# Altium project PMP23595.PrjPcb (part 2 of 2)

## Sheet DynamicLoad.SchDoc
size 431 x 279 mm; Date: Not shown in title block; ApprovedBy: Not shown in title block; CheckedBy: Not shown in title block; Author: Not shown in title block; CompanyName: Not shown in title block; Engineer: Not shown in title block; Organization: Not shown in title block; Address1: Not shown in title block; Address2: Not shown in title block; Address3: Not shown in title block; Address4: Not shown in title block; DocumentNumber: 2; Revision: Use project parameter SCH_Rev; SheetNumber: 2; SheetTotal: 3; PageSetup: Record=PageOptions¦CenterHorizontal=True¦CenterVertical=True¦PrintScale=1.00¦XCorrection=1.00¦YCorrection=1.00¦PrintKind=0¦BorderSize=5000000¦LeftOffset=0¦BottomOffset=0¦Orientation=2¦PaperLength=1000¦PaperWidth=1000¦Scale=100¦PaperSource=15¦PrintQuality=600¦MediaType=1¦DitherType=10¦PaperKind=Letter¦PrintScaleMode=1
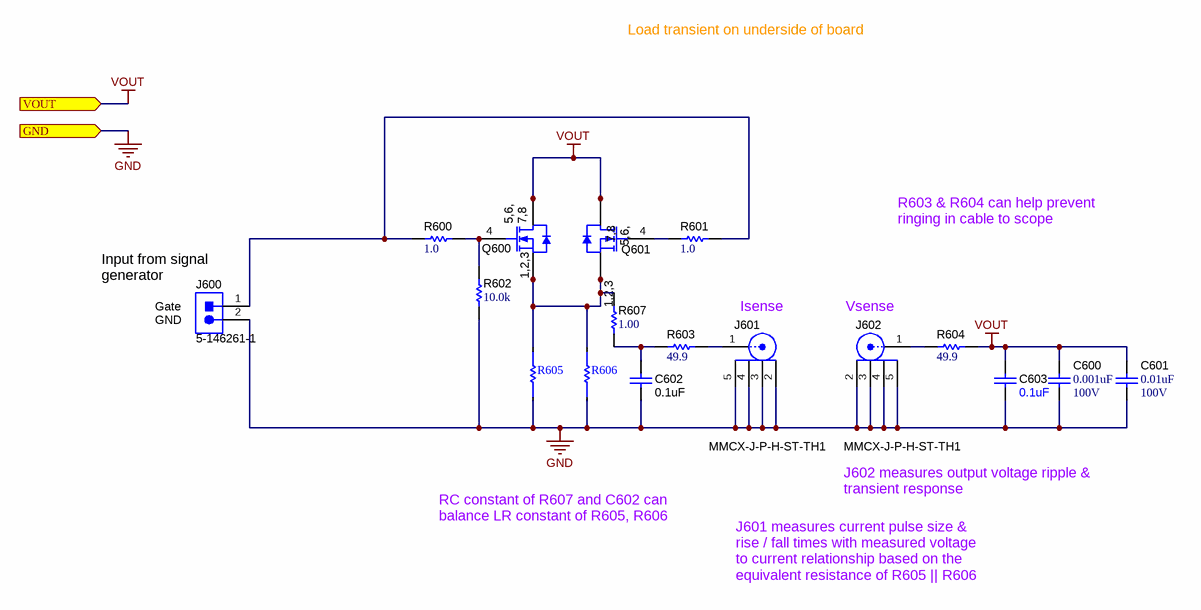
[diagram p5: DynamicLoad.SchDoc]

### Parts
C600  Cap_F: 0.001uF  VDC_V: 100V  [0603L]  (hidden comment: CGA3E2X7R2A102K080AA)
C601  Value2: 100V  ValueDisplayed: 0.01uF  [0603L]  (hidden comment: GRM188R72A103KA01D)
C602  ValueDisplayed: 0.1uF  [0603L]  (hidden comment: CGA3E2X7R1E104K080AA)
C603  ValueDisplayed: 0.1uF  [0603L]  (hidden comment: CGA3E2X7R1E104K080AA)
J600  5-146261-1  [CONN_5-146261-1]
J601  MMCX-J-P-H-ST-TH1  [Samtec_MMCX-J-P-H-ST-TH1]
J602  MMCX-J-P-H-ST-TH1  [Samtec_MMCX-J-P-H-ST-TH1]
Q600  CSD17570Q5B  [DNK0008A]  (value not drawn)
Q601  CSD17570Q5B  [DNK0008A]  (value not drawn)
R600  ValueDisplayed: 1.0  [0603L]  (hidden comment: CRCW06031R00JNEA)
R601  ValueDisplayed: 1.0  [0603L]  (hidden comment: CRCW06031R00JNEA)
R602  ValueDisplayed: 10.0k  [0603L]  (hidden comment: CRCW060310K0FKEA)
R603  ValueDisplayed: 49.9  [0603L]  (hidden comment: CRCW060349R9FKEA)
R604  ValueDisplayed: 49.9  [0603L]  (hidden comment: CRCW060349R9FKEA)
R605  WK73S3ATTER200F  [FP-WK73S3ATTER200F_1225-MFG]  (value not drawn)
R606  WK73S3ATTER200F  [FP-WK73S3ATTER200F_1225-MFG]  (value not drawn)
R607  ValueDisplayed: 1.00  [0603L]  (hidden comment: CRCW06031R00FKEA)

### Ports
GND (in), VOUT (in)

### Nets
GND: C600.2 C601.1 C602.1 C603.1 J600.2 J601.2 J601.3 J601.4 J601.5 J602.2 J602.3 J602.4 J602.5 R602.1 R605.1 R606.1 ; port GND
VOUT: C600.1 C601.2 C603.2 Q600.5(D) Q600.6(D) Q600.7(D) Q600.8(D) Q600.9(D) Q601.5(D) Q601.6(D) Q601.7(D) Q601.8(D) Q601.9(D) R604.2 ; port VOUT
NetC602_2: C602.2 R603.1 R607.1
NetJ600_1: J600.1 R600.2 R601.1
NetJ601_1: J601.1 R603.2
NetJ602_1: J602.1 R604.1
NetQ600_1: Q600.1(S) Q600.2(S) Q600.3(S) Q601.1(S) Q601.2(S) Q601.3(S) R605.2 R606.2 R607.2
NetQ600_4: Q600.4(G) R600.1 R602.2
NetQ601_4: Q601.4(G) R601.2

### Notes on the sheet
- Load transient on underside of board
- R603 & R604 can help prevent ringing in cable to scope
- (near J600) Input from signal generator
- (near J600) Gate
- (near J600) GND
- (near J601) Isense
- (near J602) Vsense
- J602 measures output voltage ripple & transient response
- RC constant of R607 and C602 can balance LR constant of R605, R606
- J601 measures current pulse size & rise / fall times with measured voltage to current relationship based on the equivalent resistance of R605 || R606

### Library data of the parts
C600 = CMP-0007081-4: CAP, CERM, 1000 pF, 100 V, +/- 10%, X7R, AEC-Q200 Grade 1, 0603; Manufacturer: TDK; TaMin_C: -55°C; ESR_ohm: 1.9714; Polarized: N; SizeAreaWB_mm2: 4.68; Value1: 1.97137 ohm; U/M: EA; Value: 1000pF; TaMax_C: 125°C; SizeZ_mm: 1; SizeX_mm: 1.6; SizeY_mm: 0.8; Cap_Case: 0603; SizeArea_mm2: 1.28; AEC Qualified: Y; IRMS_A: 305.705mA; AEC Category: Q200
C601 = CMP-0007468-5: CAP, CERM, 0.01 uF, 100 V, +/- 10%, X7R, 0603; Manufacturer: MuRata; TaMin_C: -55°C; Polarized: N; SizeAreaWB_mm2: 4.68; Value1: Unknown; U/M: EA; Value: 0.01uF; TaMax_C: 125°C; SizeZ_mm: 1; SizeX_mm: 1.6; SizeY_mm: 0.8; Cap_Case: 0603; SizeArea_mm2: 1.28; Cap_F: 10nF; AEC Category: Q200
C602 C603 = CMP-0007077-5: CAP, CERM, 0.1 uF, 25 V, +/- 10%, X7R, AEC-Q200 Grade 1, 0603; Manufacturer: TDK; TaMin_C: -55°C; Polarized: N; SizeAreaWB_mm2: 4.68; Value1: Unknown; U/M: EA; Value: 0.1uF; TaMax_C: 125°C; SizeZ_mm: 1; SizeX_mm: 1.6; SizeY_mm: 0.8; Cap_Case: 0603; Value2: 25V; SizeArea_mm2: 1.28; AEC Qualified: Y; Cap_F: 100nF; AEC Category: Q200
J600 = CMP-0054947-1: Header, 100mil, 2x1, Gold, TH; Manufacturer: TE Connectivity; Green_Lifecycle: Active; Green_REACh: Passed; CNHeader: TRUE; CT: FALSE
J601 J602 = CMP-0075554-1: Connector, MMCX 50 ohm, TH; Manufacturer: Samtec; CT: False; Gender: Female
Q600 Q601 = CMP-0000584-2: MOSFET, N-CH, 30 V, 51 A, DNK0008A (VSON-CLIP-8); Alternate Manufacturer: None; Manufacturer: Texas Instruments; SizeZ_mm: 1; ChType: N; Value2: 97 nC; Value1: 0.007; VdsMax_V: 30V; SizeX_mm: 6; SizeAreaWB_mm2: 56; SizeY_mm: 5; Vgs_V: 20V; QgTyp_nC: 97; Value: 30V; Rdson45_ohm: 7.6m; SizeArea_mm2: 30; AEC Category: Q101; IdsMax_A: 51A; U/M: EA
R600 R601 = CMP-0025743-4: RES, 1.0, 5%, 0.1 W, AEC-Q200 Grade 0, 0603; Manufacturer: Vishay-Dale; Power_W: 100mW; TempCo: 200 ppm/C; Value_Code: 1R00; Value: 1.0; EIA_Code: E24; Res_ohm: 1; SizeX_mm: 1.6; SizeY_mm: 0.8; Value2: 0.1W; SizeArea_mm2: 1.28; AEC Qualified: Y; VDC_V: 75V; AEC Category: Q200; AEC Grade: 0
R602 = CMP-0021998-4: RES, 10.0 k, 1%, 0.1 W, AEC-Q200 Grade 0, 0603; Manufacturer: Vishay-Dale; Power_W: 100mW; TempCo: 100 ppm/C; Value_Code: 10k0; Value: 10.0k; EIA_Code: E96; Res_ohm: 10k; SizeX_mm: 1.6; SizeY_mm: 0.8; SizeZ_mm: 1; Value2: 0.1W; SizeArea_mm2: 1.28; AEC Qualified: Y; VDC_V: 75V; AEC Category: Q200; AEC Grade: 0
R603 R604 = CMP-0022448-4: RES, 49.9, 1%, 0.1 W, AEC-Q200 Grade 0, 0603; Manufacturer: Vishay-Dale; Power_W: 100mW; TempCo: 100 ppm/C; Value_Code: 49R9; Value: 49.9; EIA_Code: E96; SizeX_mm: 1.6; SizeY_mm: 0.8; SizeZ_mm: 1; Value2: 0.1W; SizeArea_mm2: 1.28; AEC Qualified: Y; VDC_V: 75V; AEC Category: Q200; AEC Grade: 0
R605 R606 = CMP-0124591-1: 200 mOhms ±1% 1.5W Chip Resistor Wide 2512 (6432 Metric), 1225 Automotive AEC-Q200, Moisture Resistant Thick Film; Manufacturer: KOA Speer; AEC Grade: Grade 0; AEC Qualified: Yes; Res_ohm: 0.2; SizeZ_mm: 0.7mm; TempCo: 200ppm/°C; Value: 0.2
R607 = CMP-0022170-4: RES, 1.00, 1%, 0.1 W, AEC-Q200 Grade 0, 0603; Manufacturer: Vishay-Dale; Power_W: 100mW; TempCo: 100 ppm/C; Value_Code: 1R00; Value: 1.00; EIA_Code: E96; Res_ohm: 1; SizeX_mm: 1.6; SizeY_mm: 0.8; Value2: 0.1W; SizeArea_mm2: 1.28; AEC Qualified: Y; VDC_V: 75V; AEC Category: Q200; AEC Grade: 0

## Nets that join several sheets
AGND1: 2 (7 pins), Phase1 (14 pins), 3 (7 pins), 4 (7 pins)
GND: TopSheet (27 pins), Hardware (H700.1 H701.1 H702.1 H703.1), 2 (20 pins), Phase1 (22 pins), DynamicLoad (16 pins), 3 (20 pins), 4 (20 pins)
VCC1: 2 (C210.1 U201.2), Phase1 (5 pins), 3 (C310.1 U301.2), 4 (C410.1 U401.2)
VFILTER: TopSheet (6 pins), 2 (8 pins), Phase1 (9 pins), 3 (8 pins), 4 (8 pins)
VOUT: TopSheet (C518.1 R501.1 T501.1), 2 (14 pins), Phase1 (16 pins), DynamicLoad (14 pins), 3 (14 pins), 4 (14 pins)
COMP: TopSheet (R505.2 R506.2 R507.2), Phase1 (C123.1 R112.2 U101.21)
COMP: TopSheet (R507.1), 4 (U401.21)
COMP: TopSheet (R506.1), 3 (U301.21)
COMP: TopSheet (R505.1), 2 (U201.21)
EN/UVLO: TopSheet (J504.1 J504.4 J504.7), Phase1 (R111.1 R117.2 U101.11)
EN/UVLO: TopSheet (J504.2), 2 (C223.1 U201.11)
EN/UVLO: TopSheet (J504.5), 3 (C323.1 U301.11)
EN/UVLO: TopSheet (J504.8), 4 (C423.1 U401.11)
FPWM/SYNC: 2 (U201.13), Phase1 (U101.14)
FPWM/SYNC: 2 (U201.14), 3 (U301.13)
FPWM/SYNC: 3 (U301.14), 4 (U401.13)
FPWM/SYNC1: 2 (U201.20), Phase1 (J102.2 U101.13), 3 (U301.20), 4 (U401.20)
IMON: TopSheet (J505.2), 2 (U201.18), Phase1 (C125.1 R115.2 U101.18), 3 (U301.18), 4 (U401.18)
ISET: TopSheet (J505.4), 2 (U201.19), Phase1 (R114.2 U101.19), 3 (U301.19), 4 (U401.19)
PGOOD: TopSheet (J505.5), Phase1 (R107.1 U101.6)
VSET: TopSheet (J505.3), 2 (U201.17), Phase1 (C126.1 R121.2 U101.17), 3 (U301.17), 4 (U401.17)

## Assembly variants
001: not fitted C115 C125 C126 C219 C?2 C?3 C?4 FID1 FID2 FID3 FID4 FID5 FID6 L2 L4_S1 L4_S2 L6_S1 L6_S2 R106 R108 R109 R119 R120 R121 R124 R128 R128 R228 R307 R328 R407 R428 R? R?2 R?2 R?2 R?2 R?2 R?2 R?2 R?2 R?3 R?3 R?3 R?3 R?3 R?3 R?3 R?3 R?4 R?4 R?4 R?4 R?4 R?4 R?4 R?4 T1 T2 T3 T4 T5 T6 T7 T8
